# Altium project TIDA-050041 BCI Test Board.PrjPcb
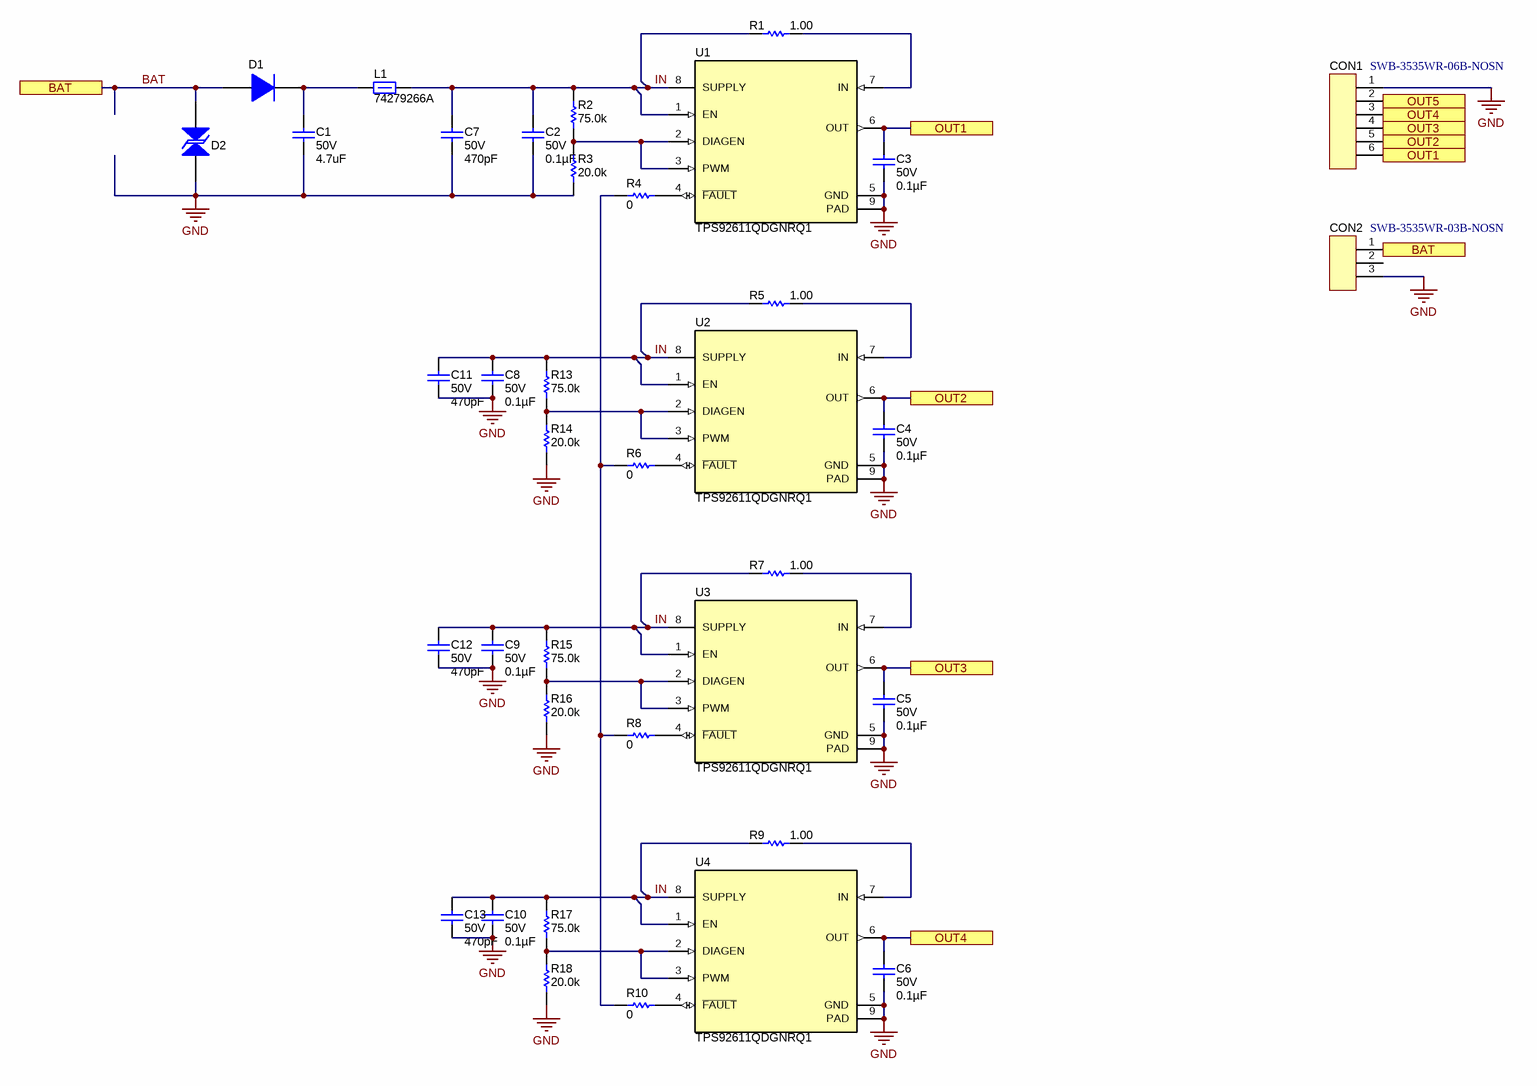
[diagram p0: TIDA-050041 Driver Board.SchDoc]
TID: TIDA-050041; TechSupport: http://www.ti.com/support; SCH_Rev: A; PRJ_Title: Change in menu Project|Project Options|Parameters; PRJ_Number: TIDA-050041 Driver Board; PRJ_Engineer: Kai Qiu; PRJ_Customer: Public Release; PCB_Rev: A; PCB_Layout: Kai Qiu; CopyrightYear: 2018
2 sheets, 46 parts. Net scope: flat (ports and power ports of the same name join across sheets).
Board file: TIDA-050041 Driver Board.PcbDoc
Sheets:
  TIDA-050041 Driver Board.SchDoc
  Sheet1.SchDoc

## Sheet TIDA-050041 Driver Board.SchDoc
size 431 x 279 mm; Date: Not shown in title block; ApprovedBy: Not shown in title block; CheckedBy: Not shown in title block; Author: Not shown in title block; CompanyName: Not shown in title block; Engineer: Not shown in title block; Organization: Not shown in title block; Address1: Not shown in title block; Address2: Not shown in title block; Address3: Not shown in title block; Address4: Not shown in title block; DocumentNumber: 1; Revision: Use project parameter SCH_Rev; SheetNumber: 2; SheetTotal: 3; PageSetup: Record=PageOptions¦CenterHorizontal=True¦CenterVertical=True¦PrintScale=1.00¦XCorrection=1.00¦YCorrection=1.00¦PrintKind=0¦BorderSize=5000000¦LeftOffset=0¦BottomOffset=0¦Orientation=2¦PaperLength=1000¦PaperWidth=1000¦Scale=100¦PaperSource=15¦PrintQuality=600¦MediaType=1¦DitherType=10¦PaperKind=Letter¦PrintScaleMode=1

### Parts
C1  VDC_V: 50V  ValueDisplayed: 4.7uF  [1206L]  (hidden comment: GRM319R61H475KA12)
C2  VDC_V: 50V  ValueDisplayed: 0.1µF  [0603L]  (hidden comment: CGA3E3X8R1H104K080AE)
C3  VDC_V: 50V  ValueDisplayed: 0.1µF  [0603L]  (hidden comment: CGA3E3X8R1H104K080AE)
C4  VDC_V: 50V  ValueDisplayed: 0.1µF  [0603L]  (hidden comment: CGA3E3X8R1H104K080AE)
C5  VDC_V: 50V  ValueDisplayed: 0.1µF  [0603L]  (hidden comment: CGA3E3X8R1H104K080AE)
C6  VDC_V: 50V  ValueDisplayed: 0.1µF  [0603L]  (hidden comment: CGA3E3X8R1H104K080AE)
C7  VDC_V: 50V  ValueDisplayed: 470pF  [0402]  (hidden comment: GRM155R71H471KA01D)
C8  VDC_V: 50V  ValueDisplayed: 0.1µF  [0603L]  (hidden comment: CGA3E3X8R1H104K080AE)
C9  VDC_V: 50V  ValueDisplayed: 0.1µF  [0603L]  (hidden comment: CGA3E3X8R1H104K080AE)
C10  VDC_V: 50V  ValueDisplayed: 0.1µF  [0603L]  (hidden comment: CGA3E3X8R1H104K080AE)
C11  VDC_V: 50V  ValueDisplayed: 470pF  [0402]  (hidden comment: GRM155R71H471KA01D)
C12  VDC_V: 50V  ValueDisplayed: 470pF  [0402]  (hidden comment: GRM155R71H471KA01D)
C13  VDC_V: 50V  ValueDisplayed: 470pF  [0402]  (hidden comment: GRM155R71H471KA01D)
CON1  SWB-3535WR-06B-NOSN  [SWB-3535 WR-06P]
CON2  SWB-3535WR-03B-NOSN  [SWB-3535 WR-03P]
D1  S1A  [SMA]  (value not drawn)
D2  SMBJ30CA-13-F  [SMB]  (value not drawn)
L1  74279266A  [WE-CBF_0603]
R1  ValueDisplayed: 1.00  [0805L]  (hidden comment: RMCF0805FT1R00)
R2  ValueDisplayed: 75.0k  [0603L]  (hidden comment: RC0603FR-0775KL)
R3  ValueDisplayed: 20.0k  [0603L]  (hidden comment: CRCW060320K0FKEA)
R4  ValueDisplayed: 0  [0603L]  (hidden comment: ERJ-3GEY0R00V)
R5  ValueDisplayed: 1.00  [0805L]  (hidden comment: RMCF0805FT1R00)
R6  ValueDisplayed: 0  [0603L]  (hidden comment: ERJ-3GEY0R00V)
R7  ValueDisplayed: 1.00  [0805L]  (hidden comment: RMCF0805FT1R00)
R8  ValueDisplayed: 0  [0603L]  (hidden comment: ERJ-3GEY0R00V)
R9  ValueDisplayed: 1.00  [0805L]  (hidden comment: RMCF0805FT1R00)
R10  ValueDisplayed: 0  [0603L]  (hidden comment: ERJ-3GEY0R00V)
R13  ValueDisplayed: 75.0k  [0603L]  (hidden comment: RC0603FR-0775KL)
R14  ValueDisplayed: 20.0k  [0603L]  (hidden comment: CRCW060320K0FKEA)
R15  ValueDisplayed: 75.0k  [0603L]  (hidden comment: RC0603FR-0775KL)
R16  ValueDisplayed: 20.0k  [0603L]  (hidden comment: CRCW060320K0FKEA)
R17  ValueDisplayed: 75.0k  [0603L]  (hidden comment: RC0603FR-0775KL)
R18  ValueDisplayed: 20.0k  [0603L]  (hidden comment: CRCW060320K0FKEA)
U1  TPS92611QDGNRQ1  [DGN0008D_N]
U2  TPS92611QDGNRQ1  [DGN0008D_N]
U3  TPS92611QDGNRQ1  [DGN0008D_N]
U4  TPS92611QDGNRQ1  [DGN0008D_N]

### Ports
BAT, OUT1, OUT2, OUT3, OUT4, OUT5

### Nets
GND: C1.2 C2.2 C3.2 C4.2 C5.2 C6.2 C7.2 C8.2 C9.2 C10.2 C11.2 C12.2 C13.2 CON1.1 CON2.3 D2.2 R3.1 R14.1 R16.1 R18.1 U1.5(GND) U1.9(PAD) U2.5(GND) U2.9(PAD) U3.5(GND) U3.9(PAD) U4.5(GND) U4.9(PAD)
BAT: CON2.1 D1.2(A) D2.1 ; port BAT
IN: C2.1 C7.1 C8.1 C9.1 C10.1 C11.1 C12.1 C13.1 L1.2 R1.1 R2.2 R5.1 R7.1 R9.1 R13.2 R15.2 R17.2 U1.1(EN) U1.8(SUPPLY) U2.1(EN) U2.8(SUPPLY) U3.1(EN) U3.8(SUPPLY) U4.1(EN) U4.8(SUPPLY)
OUT1: C3.1 CON1.6 U1.6(OUT) ; port OUT1
OUT2: C4.1 CON1.5 U2.6(OUT) ; port OUT2
OUT3: C5.1 CON1.4 U3.6(OUT) ; port OUT3
OUT4: C6.1 CON1.3 U4.6(OUT) ; port OUT4
OUT5: CON1.2 ; port OUT5
NetC1_1: C1.1 D1.1(K) L1.1
NetR1_2: R1.2 U1.7(IN)
NetR2_1: R2.1 R3.2 U1.2(DIAGEN) U1.3(PWM)
NetR4_1: R4.1 U1.4(~{FAULT})
NetR4_2: R4.2 R6.2 R8.2 R10.2
NetR5_2: R5.2 U2.7(IN)
NetR6_1: R6.1 U2.4(~{FAULT})
NetR7_2: R7.2 U3.7(IN)
NetR8_1: R8.1 U3.4(~{FAULT})
NetR9_2: R9.2 U4.7(IN)
NetR10_1: R10.1 U4.4(~{FAULT})
NetR13_1: R13.1 R14.2 U2.2(DIAGEN) U2.3(PWM)
NetR15_1: R15.1 R16.2 U3.2(DIAGEN) U3.3(PWM)
NetR17_1: R17.1 R18.2 U4.2(DIAGEN) U4.3(PWM)

Not connected (* = marked no-connect by the designer): CON2 2

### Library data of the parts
C1 = CMP-0008865-2: CAP, CERM, 4.7 uF, 50 V, +/- 10%, X5R, 1206; Manufacturer: MuRata; TaMin_C: -55°C; Polarized: N; SizeAreaWB_mm2: 10.92; Value1: Unknown; U/M: EA; Value: 4.7uF; TaMax_C: 85°C; SizeZ_mm: 1.35; SizeX_mm: 3.2; SizeY_mm: 1.6; Cap_Case: 1206; SizeArea_mm2: 5.12; CompType: Capacitor; Cap_F: 4.7µF; AEC Category: Q200
C2-C6 C8-C10 = CMP-0079911-1: CAP, CERM, 0.1 µF, 50 V,+/- 10%, X8R, AEC-Q200 Grade 0, 0603; Manufacturer: TDK; Cap_F: 100nF; SizeAreaWB_mm2: 4.68; SizeArea_mm2: 1.28; AEC Qualified: Y; AEC Category: Q200; Value: 0.1uF; TaMax_C: 150°C; SizeZ_mm: 1; AEC Grade: 0; Polarized: N; TaMin_C: -55°C; SizeY_mm: 0.8; U/M: EA; CompType: Capacitor; SizeX_mm: 1.6; Cap_Case: 0603
C7 C11-C13 = CMP-0006691-2: CAP, CERM, 470 pF, 50 V, +/- 10%, X7R, 0402; Manufacturer: MuRata; TaMin_C: -55°C; Polarized: N; SizeAreaWB_mm2: 3; Value1: Unknown; U/M: EA; Value: 470pF; TaMax_C: 125°C; SizeZ_mm: 0.6; SizeX_mm: 1; SizeY_mm: 0.5; AEC Category: Q200
CON1 = SWB-3535WR-06B-NOSN: ¹©Ó¦ÉÌ/Æ·ÅÆ Manufacturer: SWB; Æ÷¼þÃû³Æ Name: ½Ó²å¼þ
CON2 = SWB-3535WR-03B-NOSN: ¹©Ó¦ÉÌ/Æ·ÅÆ Manufacturer: SWB; Æ÷¼þÃû³Æ Name: ½Ó²å¼þ
D1 = CMP-0082549-1: Diode, Standard Recovery Rectifier, 50 V, 1 A, SMA; Manufacturer: ON Semiconductor; SizeAreaWB_mm2: 37.3428; Vr_V: 50V; SizeArea_mm2: 16.3228; AEC Qualified: N; TJmax_C: 150°C; AEC Category: Q101; Value: 50V; SizeZ_mm: 2.87; Io_A: 1A; Vf_V: 1.1V; SizeY_mm: 2.92; SizeX_mm: 5.59
D2 = CMP-0005562-2: Diode, TVS, Bi, 30 V, SMB; Manufacturer: Diodes Inc.; Power_W: 5W; SizeAreaWB_mm2: 44.156; Vr_V: 30V; U/M: EA; Value: 30V; SizeZ_mm: 2.6; SizeX_mm: 5.6; SizeY_mm: 3.81; SizeArea_mm2: 21.336; AEC Category: Q101
L1 = CMP-0003204-1: Ferrite Bead, 1000 ohm @ 100 MHz, 0.2 A, 0603; Manufacturer: Wurth Elektronik; ZTyp@100MHz_Ohm: 1k; DCR_ohm: 0.6; Value1: 0.6 ohm; Imax_A: 200mA; Value2: 0.2A
R1 R5 R7 R9 = CMP-0021975-2: RES, 1.00, 1%, 0.125 W, 0805; Manufacturer: Stackpole Electronics Inc; Power_W: 125mW; TempCo: 200 ppm/C; Value_Code: 1R00; U/M: EA; Value: 1.00; EIA_Code: E96; Res_ohm: 1; SizeX_mm: 2; SizeY_mm: 1.25; SizeZ_mm: 1.45; Value2: 0.125W; SizeArea_mm2: 2.5; CompType: Resistor; VDC_V: 150V; AEC Category: Q200
R2 R13 R15 R17 = CMP-0023267-5: RES, 75.0 k, 1%, 0.1 W, 0603; Manufacturer: Yageo; Power_W: 100mW; TempCo: 100 ppm/C; Value_Code: 75k0; Value: 75.0k; EIA_Code: E96; Res_ohm: 75k; SizeX_mm: 1.6; SizeY_mm: 0.8; SizeZ_mm: 1; Value2: 0.1W; SizeArea_mm2: 1.28; CompType: Resistor; AEC Qualified: N; VDC_V: 75V; AEC Category: Q200; SizeAreaWB_mm2: 4.68
R3 R14 R16 R18 = CMP-0022204-4: RES, 20.0 k, 1%, 0.1 W, AEC-Q200 Grade 0, 0603; Manufacturer: Vishay-Dale; Power_W: 100mW; TempCo: 100 ppm/C; Value_Code: 20k0; Value: 20.0k; EIA_Code: E96; Res_ohm: 20k; SizeX_mm: 1.6; SizeY_mm: 0.8; SizeZ_mm: 1; Value2: 0.1W; SizeArea_mm2: 1.28; CompType: Resistor; AEC Qualified: Y; VDC_V: 75V; AEC Category: Q200; AEC Grade: 0
R4 R6 R8 R10 = CMP-0025874-4: RES, 0, 5%, 0.1 W, AEC-Q200 Grade 0, 0603; Manufacturer: Panasonic; Power_W: 100mW; TempCo: 600 ppm/C; Value_Code: 0000; Value: 0; EIA_Code: E24; SizeX_mm: 1.6; SizeY_mm: 0.8; SizeZ_mm: 1; Value2: 0.1W; SizeArea_mm2: 1.28; CompType: Resistor; AEC Qualified: Y; VDC_V: 50V; AEC Category: Q200; SizeAreaWB_mm2: 4.68
U1-U4 = CMP-0065147-2: Automotive Single Channel LED Driver, DGN0008D (VSSOP-8); Manufacturer: Texas Instruments; SizeX_mm: 5.05; SizeY_mm: 3.1; CompType: IC; SizeZ_mm: 1.1; SizeArea_mm2: 15.655; SizeAreaWB_mm2: 35.955; U/M: EA

## Sheet Sheet1.SchDoc
size Letter; Date: Not shown in title block; ApprovedBy: Not shown in title block; CheckedBy: Not shown in title block; Author: Not shown in title block; CompanyName: Not shown in title block; Engineer: Not shown in title block; Organization: Not shown in title block; Address1: Not shown in title block; Address2: Not shown in title block; Address3: Not shown in title block; Address4: Not shown in title block; DocumentNumber: 2; Revision: Use project parameter SCH_Rev; SheetNumber: 2; SheetTotal: 3; PageSetup: Record=PageOptions¦CenterHorizontal=True¦CenterVertical=True¦PrintScale=1.00¦XCorrection=1.00¦YCorrection=1.00¦PrintKind=0¦BorderSize=5000000¦LeftOffset=0¦BottomOffset=0¦Orientation=2¦PaperLength=1000¦PaperWidth=1000¦Scale=100¦PaperSource=15¦PrintQuality=600¦MediaType=1¦DitherType=10¦PaperKind=Letter¦PrintScaleMode=1
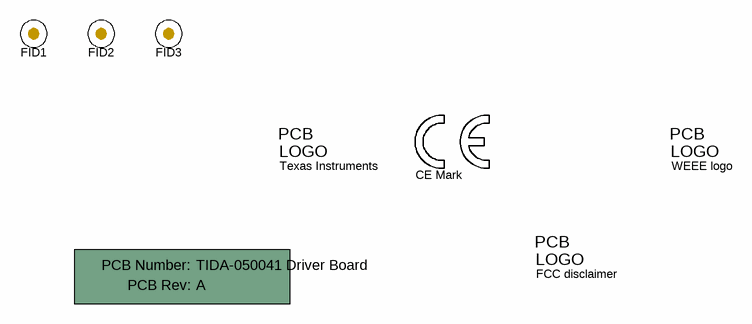
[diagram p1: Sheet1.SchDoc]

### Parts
FID1  Fiducial  [Fiducial10-20]  (value not drawn)
FID2  Fiducial  [Fiducial10-20]  (value not drawn)
FID3  Fiducial  [Fiducial10-20]  (value not drawn)
Logo1  CE Mark  [CE_Mark_5mm]  (no BOM)
Logo2  Texas Instruments  [TI_Stacked_Overlay_Small]  (no BOM)
Logo4  WEEE logo  [WEEE_Minimum]  (no BOM)
Logo?  FCC disclaimer  [FCC_disclaimer]  (no BOM)
TIDA-050041  Printed Circuit Board  (value not drawn)  (mechanical)

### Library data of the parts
FID1-FID3 = CMP-0077181-1: Fiducial mark.  There is nothing to buy or mount.
Logo1 = CMP-0074844-1: SymbolCreator: a0412235
Logo2 = CMP-0074838-1: Texas Instrument Corporate Signature; SymbolCreator: a0412235; Lib Reference: TI_Logo; Library Reference: Logo
Logo4 = CMP-0074769-1
Logo? = CMP-0074847-1: FCC_disclaimer; Library Reference: Logo
TIDA-050041 = CMP-0003618-2: Manufacturer: Any; PartNumber: TIDA-050041

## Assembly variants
001: not fitted FID1 FID2 FID3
